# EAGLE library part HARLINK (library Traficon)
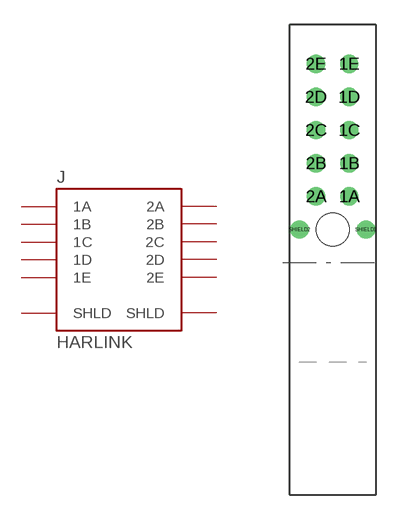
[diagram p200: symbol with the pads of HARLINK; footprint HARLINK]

Designator prefix J

## HARLINK  [HARLINK]
1A  1A  pas
1B  1B  pas
1C  1C  pas
1D  1D  pas
1E  1E  pas
2A  2A  pas
2B  2B  pas
2C  2C  pas
2D  2D  pas
2E  2E  pas
SHIELD1  SHLD  pas
SHIELD2  SHLD  pas

## Footprint HARLINK (pad centres in mm)
drill 0.6 round: 1A 1,2; 1B 1,4; 1C 1,6; 1D 1,8; 1E 1,10; 2A -1,2; 2B -1,4; 2C -1,6; 2D -1,8; 2E -1,10; SHIELD1 2,0; SHIELD2 -2,0
hole 2 at 0,0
